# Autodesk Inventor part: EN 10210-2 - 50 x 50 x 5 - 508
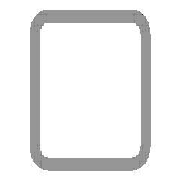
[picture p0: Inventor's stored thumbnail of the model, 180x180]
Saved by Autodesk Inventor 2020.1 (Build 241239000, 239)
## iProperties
Created: 2019-10
Part Number: EN 10210-2 - 50 x 50 x 5 - 508
Material: Stahl, weich
Description: Rohrleitung
Document SubType Name: Modeling
Standard: DIN
Designer: lutzd
Standard Revision: 2006-07
Standards Organization: DIN
Language: de-DE
Size Designation: 50 x 50 x 5
Categories: <MemberInstance><Categories><Category DisplayName="Profile" InternalName="089c4875-fa83-4c05-b084-43b9cc11f5ed" Mnemonic="GRDR"><CategoryParameter DisplayName="
Stock Number: 50 x 50 x 5
Mass: 3479.32 g
Surface Area: 1737.95 cm^2
Volume: 443.226 cm^3
Density: 7.85 g/cm^3
Appearance: Halbpoliert
_CCFamilyMember: 16
_CCFamilyDisplayName: DIN EN 10210-2 (USAS B17.1 quadratisch) - Rohrleitung — In Klammern angegebene Größen wurden aufgehoben
_FrameMemberDoc: Frame Member File
_Version: 15.0.0
_GetPNFromCC: 1
G_L: 508,000 mm
G_W: 50,000 mm
G_H: 50,000 mm
Dimensions: 50x50x508 mm
Mass: 3,479 kg
+002C4D88-41F6-452C-BA8C-33060BDDF813+SCHNITTDETAIL1: Schnittwinkel 90,00 grd
+BC83CCC9-9F0D-44AB-B8C7-8E35FEEBA003+SCHNITTDETAIL2: Schnittwinkel 90,00 grd
DocNumber: ADSK-014150
Folder: .
IsCustomPart: 1
Title: Profil-Bauteil
Author: lutzd
Revision Number: -
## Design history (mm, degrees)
node "Startebene"
node "Endebene"
sketch "Skizze"
  geometry: L1 (-25, -17.5)-(-25, 17.5); L2 (-17.5, 25)-(17.5, 25); L3 (25, 17.5)-(25, -17.5); L4 (17.5, -25)-(-17.5, -25); L5 (-15, 20)-(15, 20); L6 (20, 15)-(20, -15); L7 (15, -20)-(-15, -20); L8 (-20, -15)-(-20, 15); L9 (0, 37.175)-(0, -37.175) reference; L10 (-37.175, 0)-(37.175, 0) reference; A1 r 7.5 centre (-17.5, -17.5) between (-25, -17.5) and (-17.5, -25); A2 r 7.5 centre (-17.5, 17.5) between (-17.5, 25) and (-25, 17.5); A3 r 7.5 centre (17.5, 17.5) between (25, 17.5) and (17.5, 25); A4 r 7.5 centre (17.5, -17.5) between (17.5, -25) and (25, -17.5); A5 r 5 centre (-15, -15) between (-20, -15) and (-15, -20); A6 r 5 centre (-15, 15) between (-15, 20) and (-20, 15); A7 r 5 centre (15, 15) between (20, 15) and (15, 20); A8 r 5 centre (15, -15) between (15, -20) and (20, -15)
  constraints: 16 end point, 16 point on circle, 16 tangent, 8 centre point, 6 equal radius, 4 parallel, 2 perpendicular, 2 other
  dimensions: "d7" = 7.5 radius of A1 (= G_IR); "d10" = 50 distance between parallel lines of L2 L4 (= G_H); "d11" = 50 distance between parallel lines of L1 L3 (= G_W); "d12" = 5 distance between parallel lines of L3 L6 (= G_T); "d15" = 25 distance between parallel lines of L2 L10 (= 0.5 x d10); "d16" = 25 distance between parallel lines of L9 L3 (= 0.5 x d11); "d19" = 5 radius of A5 (= G_T); "d20" = 5 distance between parallel lines of L4 L7 (= G_T)
extrude "Körper" new body sketch "Skizze" stored distance "d3" = 508 (= G_L); taper "d4" = 0 deg
node "Driven Length"
  sketch "Sketch3"
    geometry: L1 (0, 0)-(10, 0) reference
    constraints: 2 end point, 1 horizontal
  workplane "Work Plane3"
  sketch "Sketch4"
    geometry: L1 (-2, 25)-(12, 25) reference; L2 (-2, 533)-(12, 533) reference
    dimensions: "d18" = 508 distance between parallel lines of L1 L2 (derived)
workplane "Arbeitsebene4"
feature "Trennen1"
workplane "Arbeitsebene5"
feature "Trennen2"
sketch "Skizze5"
  geometry: L1 (35, 508)-(0, 508) reference; L2 (17.5, 508)-(17.5, 32); 3 further points
  constraints: 2 end point, 1 coincident, 1 midpoint, 1 point on line, 1 vertical
  dimensions: "d21" = 96 distance of point (17.5, 128) point (17.5, 32); "d22" = 380 distance of L2.start point (17.5, 128)
hole "Bohrung1" sketch "Skizze5" at (17.5, 32), (17.5, 128) diameter "d23" = 6.647; stored, may be unused: countersink angle "d27" = 90 deg, drill point angle "d29" = 0 deg; dims "d24" = 16, "d25" = 4, "d26" = 2, "d28" = 8
body "Solid1"
other parameters: "G_W" = 50 [user parameter; used in 1 equation term], "G_H" = 50 [user parameter; used in 1 equation term], "G_T" = 5 [user parameter; used in 3 equation terms], "G_IR" = 7.5 [user parameter; used in 1 equation term], "G_L" = 508 (= d18) [user parameter; used in 1 equation term], "G_OFFSET_START" = -25 [user parameter; used in 1 equation term], "d13" = 25 (= -G_OFFSET_START), "d14" = 533 (= G_OFFSET_END + B_L), "B_L" = 583 [user parameter; used in 1 equation term], "d17" = 90 deg
